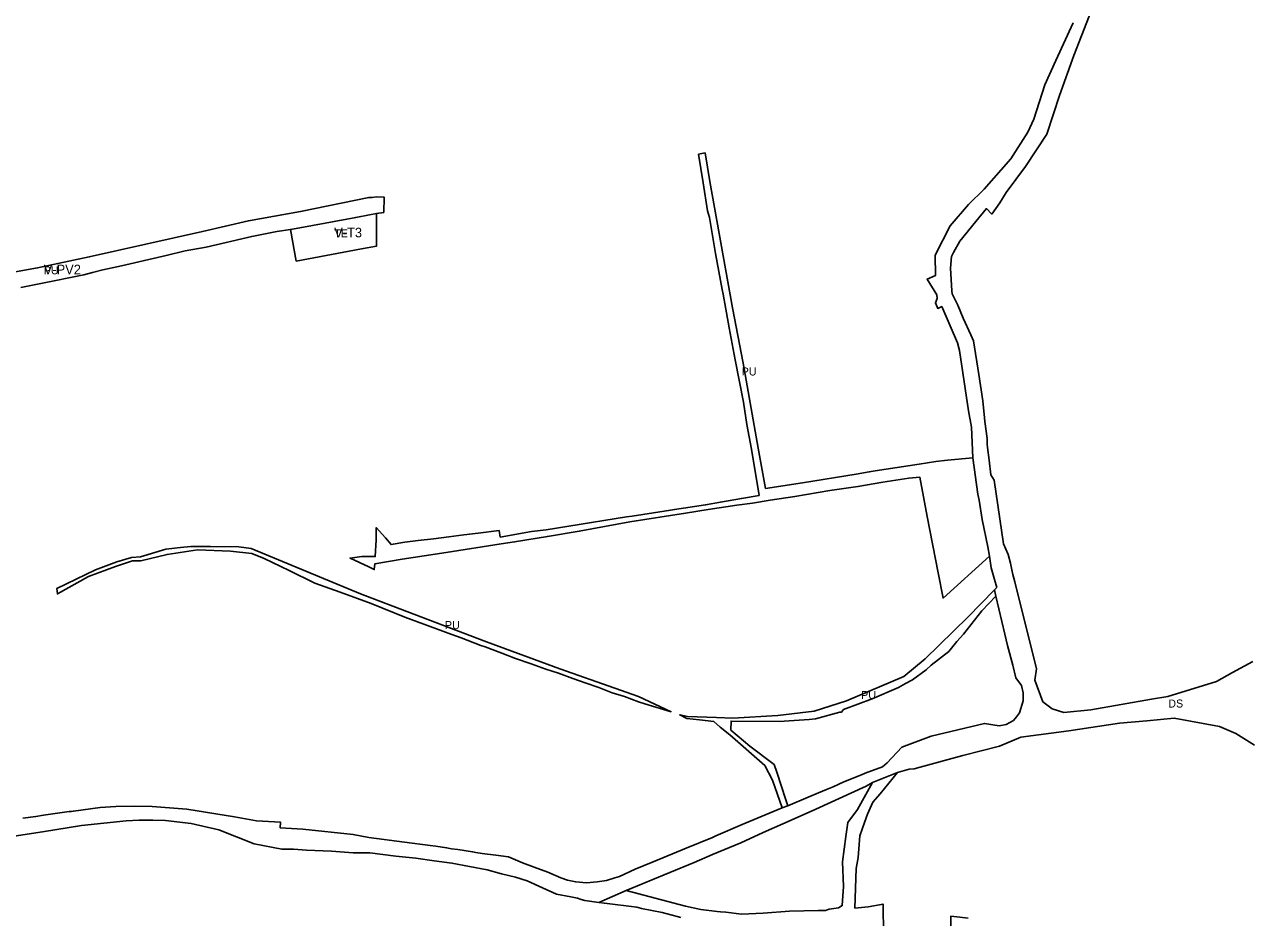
# Model space of a CAD drawing. Extents: x -532083 to -529750, y -1178838 to -1176858.
# Drawn here: x -531640 to -530875, y -1178450 to -1177892 of the extents above; entities that cross this region are included whole.
import ezdxf

# ---------------------------------------------------------------- set-up
doc = ezdxf.new("R2010")
doc.units = 0
for name, color, linetype in [('90320013', 7, 'Continuous'), ('90400023', 7, 'Continuous'), ('90450013', 7, 'Continuous'), ('90450023', 7, 'Continuous'), ('ID_navrh', 7, 'Continuous')]:
    doc.layers.add(name, color=color, linetype=linetype)

msp = doc.modelspace()

# ---------------------------------------------------------------- linework, layer by layer
at = {"layer": '90320013'}
for points in [[(-530959.2033, -1177846.27645), (-530984.6873, -1177911.73145), (-530993.4503, -1177936.65945), (-531001.4993, -1177960.86645), (-531014.8703, -1177980.98445), (-531026.9673, -1177997.27045), (-531030.7873, -1178003.65745), (-531035.8703, -1178010.69345), (-531039.2753, -1178007.27745), (-531045.8343, -1178015.24845), (-531055.9243, -1178027.64645), (-531059.7083, -1178034.60445), (-531061.0953, -1178037.26145), (-531061.6003, -1178044.47245), (-531060.8023, -1178058.56645), (-531060.5533, -1178060.43945), (-531057.0003, -1178067.52345), (-531053.7083, -1178075.79545), (-531048.9563, -1178086.17245), (-531047.3693, -1178089.85545), (-531043.9953, -1178110.85545), (-531041.5613, -1178127.31645), (-531040.4163, -1178138.03445), (-531040.1223, -1178140.29745), (-531038.7793, -1178150.89845), (-531038.7793, -1178154.31245), (-531038.5823, -1178156.55945), (-531037.6013, -1178164.35645), (-531036.4443, -1178173.56145), (-531034.3293, -1178176.83645), (-531028.4563, -1178216.54745), (-531025.7063, -1178223.39945), (-531024.2163, -1178228.68245), (-531023.0313, -1178233.88745), (-531022.7053, -1178235.84845), (-531021.4783, -1178240.47345), (-531007.9793, -1178294.81445), (-531009.0453, -1178301.76245), (-531003.8943, -1178315.30345), (-530998.0323, -1178319.75745), (-530990.7503, -1178322.07345), (-530973.8763, -1178320.29145), (-530955.0093, -1178317.00945), (-530936.1423, -1178313.72745), (-530925.7413, -1178311.91845), (-530895.3683, -1178302.65345), (-530885.4993, -1178296.92945), (-530872.6603, -1178290.05245)], [(-531641.3883, -1178387.99745), (-531633.4203, -1178386.90845), (-531628.6483, -1178386.19045), (-531612.4223, -1178383.79645), (-531611.1353, -1178383.80445), (-531609.9043, -1178383.52845), (-531593.0393, -1178381.35445), (-531583.2593, -1178380.60045), (-531571.7863, -1178380.41145), (-531560.6903, -1178380.60045), (-531538.8733, -1178382.29845), (-531509.0893, -1178387.21045), (-531495.4553, -1178389.57445), (-531480.4153, -1178390.53545), (-531480.6073, -1178394.10845), (-531466.5523, -1178394.88145), (-531435.0033, -1178398.26045), (-531425.2643, -1178400.01845), (-531402.8663, -1178402.94945), (-531386.8943, -1178405.09845), (-531383.3893, -1178405.48845), (-531376.5723, -1178406.46545), (-531373.4553, -1178407.05145), (-531369.5603, -1178407.63845), (-531360.4063, -1178409.00545), (-531358.2633, -1178409.39645), (-531354.3193, -1178409.99545), (-531345.8613, -1178411.02445), (-531337.9163, -1178412.05245), (-531329.2023, -1178415.90845), (-531321.7883, -1178418.53745), (-531313.2443, -1178421.69445), (-531305.1503, -1178425.30345), (-531301.1033, -1178426.65645), (-531295.9323, -1178427.78345), (-531289.1853, -1178428.36345), (-531282.4223, -1178427.76045), (-531276.7113, -1178426.85545), (-531271.4503, -1178425.19745), (-531268.5953, -1178424.44345), (-531258.8263, -1178419.92145), (-531247.5543, -1178415.24745), (-531226.9643, -1178406.80545), (-531210.4323, -1178400.02145), (-531208.3283, -1178398.96645), (-531191.7963, -1178392.03145), (-531166.8483, -1178381.62945), (-531163.3583, -1178380.31945), (-531150.7163, -1178374.88445), (-531139.1693, -1178370.13345), (-531134.9143, -1178368.31745), (-531128.3683, -1178365.37445), (-531117.3063, -1178360.84545), (-531115.0493, -1178359.93945), (-531104.0813, -1178355.94045), (-531101.3573, -1178353.43545), (-531092.0493, -1178343.64445), (-531073.6623, -1178336.81345), (-531040.5193, -1178328.84345), (-531031.2123, -1178330.20945), (-531026.8993, -1178329.52645), (-531022.3593, -1178327.02245), (-531020.4293, -1178324.63145), (-531018.5003, -1178322.24045), (-531016.2303, -1178314.72645), (-531016.2303, -1178309.71645), (-531017.3653, -1178305.16245), (-531020.7703, -1178300.38045), (-531022.8133, -1178292.41145), (-531026.0043, -1178280.13145), (-531027.7303, -1178273.15745), (-531033.2923, -1178249.40845), (-531034.2153, -1178245.46645), (-531032.7923, -1178244.01445), (-531034.2173, -1178238.96245), (-531036.2663, -1178231.69545), (-531037.2013, -1178224.41145), (-531038.4003, -1178218.55645), (-531041.8943, -1178201.45545), (-531043.8503, -1178189.40045), (-531044.5493, -1178185.61545), (-531047.6373, -1178162.97345), (-531048.6323, -1178143.75845), (-531050.3733, -1178133.52745), (-531056.1393, -1178095.84445), (-531057.3783, -1178091.04945), (-531067.1173, -1178068.49245), (-531069.6673, -1178069.63745), (-531071.0823, -1178066.03545), (-531069.9503, -1178063.51945), (-531070.3053, -1178061.21045), (-531076.3253, -1178051.44145), (-531071.0403, -1178049.03745), (-531071.2613, -1178036.44645), (-531061.7913, -1178018.11045), (-531050.3393, -1178004.63545), (-531040.6493, -1177995.13645), (-531023.9113, -1177976.13845), (-531013.3403, -1177959.57045), (-531009.5663, -1177951.31145), (-531002.8073, -1177929.87745), (-530995.8013, -1177914.67845), (-530985.0123, -1177891.27045)], [(-530871.6293, -1178342.35045), (-530883.3793, -1178335.06145), (-530893.4913, -1178330.80845), (-530921.8693, -1178325.57345), (-530938.9643, -1178327.11345), (-530956.0633, -1178328.65445), (-530987.6533, -1178333.42645), (-531017.7223, -1178337.43545), (-531031.0433, -1178342.97145), (-531054.0703, -1178348.88845), (-531080.7133, -1178356.14245), (-531084.3593, -1178357.13545), (-531087.5903, -1178357.47745), (-531094.8463, -1178359.38345), (-531110.3283, -1178365.64845), (-531114.3473, -1178367.92645), (-531145.7983, -1178382.29845), (-531159.4583, -1178388.35945), (-531178.7973, -1178397.00045), (-531192.6863, -1178403.34945), (-531210.4433, -1178410.75645), (-531221.8713, -1178415.69445), (-531236.9913, -1178421.86645), (-531264.4173, -1178433.15345), (-531281.4903, -1178440.54845), (-531290.2363, -1178439.37845), (-531292.5683, -1178438.69645), (-531294.9013, -1178438.01445), (-531298.9823, -1178437.03945), (-531307.9233, -1178435.47945), (-531316.6693, -1178431.58045), (-531326.1933, -1178427.09645), (-531333.5793, -1178424.75645), (-531342.3063, -1178422.67945), (-531351.3013, -1178420.33945), (-531373.2873, -1178415.99545), (-531384.2813, -1178414.65945), (-531395.9403, -1178412.98845), (-531408.2663, -1178411.65145), (-531424.5903, -1178409.64645), (-531434.9173, -1178409.64645), (-531448.5753, -1178408.64445), (-531464.2323, -1178407.97645), (-531472.2273, -1178407.30745), (-531479.5563, -1178407.30745), (-531496.8793, -1178403.96645), (-531518.8663, -1178395.27845), (-531536.2743, -1178391.25045), (-531552.2093, -1178389.45845), (-531560.1773, -1178389.32145), (-531568.6953, -1178389.18345), (-531576.9383, -1178389.59645), (-531604.7423, -1178392.64145), (-531629.1453, -1178396.55945), (-531646.7993, -1178399.28445)]]:
    msp.add_lwpolyline(points, dxfattribs=at)
at = {"layer": '90400023'}
msp.add_lwpolyline([(-531429.7583, -1178032.40945), (-531470.5433, -1178040.03745), (-531474.2493, -1178020.22145), (-531466.0373, -1178018.84845), (-531433.3573, -1178012.73645), (-531424.8033, -1178011.20645), (-531420.3633, -1178010.41245), (-531420.3633, -1178030.72945)], close=True, dxfattribs=at)
at = {"layer": '90450013'}
for points in [[(-531181.9603, -1178156.86045), (-531177.2663, -1178182.05345), (-531154.2633, -1178178.52145), (-531120.7303, -1178173.04145), (-531112.4833, -1178171.69345), (-531108.7283, -1178170.98745), (-531081.2653, -1178166.98445), (-531070.7733, -1178165.21945), (-531063.5583, -1178164.47145), (-531047.6373, -1178162.97345), (-531044.5493, -1178185.61545), (-531043.8503, -1178189.40045), (-531041.8943, -1178201.45545), (-531038.4003, -1178218.55645), (-531037.2013, -1178224.41145), (-531066.3413, -1178250.50545), (-531069.3933, -1178234.82645), (-531076.2633, -1178199.53545), (-531080.7733, -1178175.10645), (-531087.6883, -1178175.70945), (-531103.9253, -1178178.12245), (-531119.5603, -1178180.83645), (-531137.0783, -1178183.28645), (-531158.9223, -1178187.00745), (-531174.3783, -1178189.28145), (-531185.5063, -1178191.14145), (-531195.1923, -1178192.58845), (-531213.1213, -1178195.27545), (-531227.3753, -1178197.43345), (-531262.1623, -1178202.95445), (-531293.6743, -1178208.82545), (-531313.6463, -1178212.00845), (-531334.1103, -1178215.47745), (-531342.4243, -1178216.58945), (-531376.7873, -1178222.14945), (-531404.3153, -1178226.22645), (-531421.4963, -1178229.19145), (-531421.8663, -1178232.71245), (-531425.1913, -1178231.04445), (-531436.9273, -1178225.55645), (-531429.6903, -1178224.59645), (-531421.2193, -1178224.59645), (-531420.5903, -1178214.14045), (-531420.5903, -1178206.52645), (-531414.8453, -1178212.88345), (-531411.3353, -1178217.14545), (-531402.6503, -1178215.53445), (-531394.3873, -1178214.49845), (-531384.7963, -1178213.46245), (-531375.2053, -1178212.27845), (-531365.9093, -1178211.09445), (-531356.9083, -1178210.05845), (-531343.7753, -1178208.28245), (-531343.0373, -1178212.42645), (-531323.5853, -1178209.00045), (-531314.3153, -1178207.81345), (-531300.3103, -1178205.63745), (-531264.2193, -1178199.80945), (-531260.6093, -1178199.32645), (-531240.7183, -1178196.28945), (-531231.4533, -1178194.83245), (-531228.5193, -1178194.37145), (-531214.7953, -1178192.28545), (-531205.4373, -1178190.61645), (-531192.3363, -1178188.32245), (-531181.3153, -1178186.44545), (-531186.0983, -1178157.45145), (-531189.0523, -1178142.11245), (-531191.0893, -1178128.24845), (-531196.1823, -1178101.64045), (-531200.0493, -1178081.64945), (-531203.6973, -1178060.78645), (-531204.3943, -1178057.75545), (-531208.5783, -1178035.37745), (-531212.2963, -1178012.76545), (-531213.4583, -1178008.56945), (-531216.2473, -1177991.08545), (-531219.0823, -1177973.31545), (-531215.0533, -1177972.48845), (-531212.0083, -1177990.43145), (-531197.9833, -1178069.27145), (-531191.3503, -1178103.88845)], [(-531498.8093, -1178219.47445), (-531430.5003, -1178247.87745), (-531401.3843, -1178258.95045), (-531351.6793, -1178277.88245), (-531305.8513, -1178294.69545), (-531271.5133, -1178306.88845), (-531256.6233, -1178312.06945), (-531236.2643, -1178321.51945), (-531252.6733, -1178316.64245), (-531256.6233, -1178315.42245), (-531265.4363, -1178312.06945), (-531273.0333, -1178309.63145), (-531281.5433, -1178306.45245), (-531290.0873, -1178303.52045), (-531297.6473, -1178300.79145), (-531306.7633, -1178297.43845), (-531314.6643, -1178295.00045), (-531323.7803, -1178291.64745), (-531333.5043, -1178288.29445), (-531342.0133, -1178284.94145), (-531352.5763, -1178280.94145), (-531355.2663, -1178280.22145), (-531367.4623, -1178275.36445), (-531370.5113, -1178274.28445), (-531373.2833, -1178273.27745), (-531382.8873, -1178269.78745), (-531402.7953, -1178262.41045), (-531423.7793, -1178253.95545), (-531443.0743, -1178246.85345), (-531458.8913, -1178241.15845), (-531475.1133, -1178233.22545), (-531490.7263, -1178225.90345), (-531498.3923, -1178222.64945), (-531511.7753, -1178221.22545), (-531532.2563, -1178220.41145), (-531551.3173, -1178223.25945), (-531567.7413, -1178227.32745), (-531573.0133, -1178227.32745), (-531583.5583, -1178230.78545), (-531600.3883, -1178237.09045), (-531619.8553, -1178247.87045), (-531620.2603, -1178244.61645), (-531596.1303, -1178232.81945), (-531582.7243, -1178227.92845), (-531573.4793, -1178225.20045), (-531567.9053, -1178224.79145), (-531552.1343, -1178220.01845), (-531543.0253, -1178218.92745), (-531536.5003, -1178218.24545), (-531532.3623, -1178218.24545), (-531524.2643, -1178218.24545), (-531506.4883, -1178218.51145)], [(-531130.8513, -1178321.67245), (-531145.9763, -1178325.97445), (-531150.0393, -1178326.42745), (-531168.7763, -1178327.55945), (-531198.7993, -1178327.33245), (-531199.0253, -1178332.99345), (-531187.0613, -1178342.95745), (-531171.9363, -1178354.50545), (-531170.1433, -1178359.24045), (-531164.5013, -1178376.63145), (-531163.3583, -1178380.31945), (-531166.8483, -1178381.62945), (-531172.9913, -1178364.33545), (-531177.6413, -1178355.16845), (-531199.6073, -1178336.02945), (-531205.5403, -1178331.04345), (-531209.5483, -1178327.66645), (-531218.5273, -1178326.54045), (-531226.5443, -1178325.73645), (-531230.8733, -1178323.48445), (-531225.9733, -1178324.41445), (-531207.8503, -1178325.00645), (-531197.8043, -1178325.59945), (-531169.6343, -1178323.82145), (-531146.9793, -1178321.25245), (-531126.6893, -1178314.73145), (-531090.8373, -1178299.51645), (-531077.4413, -1178288.45145), (-531050.8823, -1178262.47845), (-531034.2153, -1178245.46645), (-531033.2923, -1178249.40845), (-531042.1083, -1178258.48345), (-531053.4583, -1178272.96345), (-531057.6743, -1178277.56045), (-531062.7133, -1178283.82845), (-531073.6623, -1178292.41145), (-531076.8403, -1178295.37145), (-531085.4663, -1178301.51945), (-531089.8883, -1178303.97145), (-531094.0923, -1178306.30145), (-531110.6643, -1178313.35945), (-531128.5973, -1178320.19045), (-531129.7223, -1178321.67245)]]:
    msp.add_lwpolyline(points, close=True, dxfattribs=at)
for points in [[(-531230.1783, -1178450.10145), (-531232.5303, -1178449.47245), (-531241.8403, -1178446.98245), (-531254.8623, -1178444.44745), (-531257.7783, -1178443.66745), (-531277.9913, -1178441.13345), (-531281.4903, -1178440.54845), (-531264.4173, -1178433.15345), (-531227.3213, -1178443.02945), (-531217.6513, -1178444.96945), (-531207.4543, -1178446.20345), (-531205.3453, -1178446.38045), (-531202.0743, -1178446.73645), (-531192.4053, -1178447.86745), (-531178.7063, -1178447.38245), (-531162.3323, -1178446.03545), (-531144.3003, -1178445.59845), (-531139.7933, -1178445.59845), (-531137.4343, -1178444.87745), (-531131.7693, -1178444.02445), (-531129.3233, -1178442.53445), (-531128.4503, -1178430.57445), (-531129.2453, -1178415.19245), (-531127.0263, -1178399.46445), (-531125.8593, -1178390.62245), (-531119.8453, -1178382.49245), (-531110.3283, -1178365.64845), (-531094.8463, -1178359.38345), (-531105.5563, -1178372.72645), (-531110.1543, -1178377.91745), (-531113.4733, -1178385.45345), (-531115.3953, -1178390.71145), (-531118.3273, -1178398.91645), (-531119.3053, -1178412.48345), (-531120.5863, -1178419.51345), (-531121.4503, -1178444.11945), (-531113.1583, -1178443.25345), (-531103.8303, -1178441.67045), (-531103.7443, -1178445.71145), (-531103.5033, -1178456.95545)], [(-531061.4353, -1178461.18745), (-531061.4353, -1178449.10445), (-531055.8573, -1178449.82945), (-531050.6423, -1178450.37045)]]:
    msp.add_lwpolyline(points, dxfattribs=at)
at = {"layer": '90450023'}
msp.add_lwpolyline([(-531657.8963, -1178048.92645), (-531632.1983, -1178044.31545), (-531600.0023, -1178037.41445), (-531529.1933, -1178021.60045), (-531500.4653, -1178014.88645), (-531467.8423, -1178009.01245), (-531425.3063, -1178000.34745), (-531423.1153, -1178000.28945), (-531420.3633, -1177999.98245), (-531415.7293, -1178000.11345), (-531415.9013, -1178009.61445), (-531420.3633, -1178010.41245), (-531424.8033, -1178011.20645), (-531433.3573, -1178012.73645), (-531466.0373, -1178018.84845), (-531474.2493, -1178020.22145), (-531482.6533, -1178021.62645), (-531498.4403, -1178024.68245), (-531526.9653, -1178031.34945), (-531539.9823, -1178033.57145), (-531551.8913, -1178036.62745), (-531579.8623, -1178043.01645), (-531591.4943, -1178045.51745), (-531597.8643, -1178047.18345), (-531603.4033, -1178048.57245), (-531630.2673, -1178054.12845), (-531642.7123, -1178056.59445)], dxfattribs=at)

# ---------------------------------------------------------------- texts
at = {"layer": '90320013'}
msp.add_text('DS', height=5, rotation=0.00000002, dxfattribs=at).set_placement((-530925.5543, -1178318.88341))
at = {"layer": '90400023'}
msp.add_text('TE', height=5, rotation=359.99999999, dxfattribs=at).set_placement((-531446.83842, -1178025.22495))
at = {"layer": '90450013'}
for rotation, p in [(0.00000006, (-531192.14864, -1178111.49695)), (359.99999999, (-531377.65438, -1178269.88245)), (0.00000001, (-531117.52985, -1178313.54795))]:
    msp.add_text('PU', height=5, rotation=rotation, dxfattribs=at).set_placement(p)
at = {"layer": '90450023'}
msp.add_text('PU', height=5, rotation=359.99999996, dxfattribs=at).set_placement((-531628.38218, -1178048.30445))
at = {"layer": 'ID_navrh'}
for s, p in [('V-T3', (-531446.83842, -1178025.22495)), ('V-PV2', (-531628.38218, -1178048.30445))]:
    msp.add_text(s, height=6, rotation=0.00000002, dxfattribs=at).set_placement(p)

doc.saveas('drawing.dxf')
